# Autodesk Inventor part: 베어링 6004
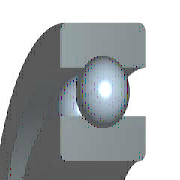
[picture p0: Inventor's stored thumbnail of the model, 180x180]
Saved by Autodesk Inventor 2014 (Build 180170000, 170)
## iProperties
IsCustomPart: 1
Created: 2012-02
Part Number: 베어링 6004
Material: 강철, 연강
Description: 깊은 그루브 볼 베어링
Document SubType Name: Modeling
Standard: KS B 2023
Designer: mduedu
Standards Organization: KS
Language: ko-KR
Size Designation: 6004 - 20 x 42 x 12
Categories: <MemberInstance><Categories><Category DisplayName="샤프트 부품" InternalName="7f7aeb1f-a693-4053-b835-cee3144e0d98" Mnemonic="SHFT"><Category DisplayName="베어링" Inter
Density: 1 g/cm^3
Appearance: Yellow
Author: mduedu
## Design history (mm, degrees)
sketch "스케치" dims "d0" = 5.72 (= -0.26 x WD + 0.26 x BD)
  geometry: L1 (3.14, 15.5)-(8.86, 15.5); L2 (6, 15.5)-(6, 12.64); L3 (6, 15.5)-(6, 18.36); L4 (3.875, 13.586)-(0, 13.586); L5 (0, 10)-(12, 10); L6 (3.875, 17.414)-(0, 17.414); L7 (0, 21)-(12, 21); L8 (12, 10)-(12, 13.586); L9 (8.125, 13.586)-(12, 13.586); L10 (8.125, 17.414)-(12, 17.414); L11 (12, 21)-(12, 17.414); L12 (-1.4, 0)-(8.4, 0) reference; L13 (0, -0.3)-(0, 5.3) reference
  constraints: 22 end point, 4 point on line, 2 collinear, 2 perpendicular, 2 symmetric about line, 1 midpoint, 1 parallel, 14 other
  dimensions: "d9" = 20 diameter of L5 L12 (= WD); "d11" = 42 diameter of L7 L12 (= BD); "d12" = 12 distance between parallel lines of L8 L13 (= KB); "d13" = 27.172 diameter of L9 L12 (= 0.326 x BD + 0.674 x WD)
revolve "본체" stored, may be unused: angle "d6" = 90 deg
revolve "볼" stored, may be unused: angle "d7" = 90 deg
pattern_circular "IDS_ARRAYBALL[SIMPL:T]" dims angle "d3" = 360 deg
body "Solid1"
fillet "모깎기1" dims "d1" = 0.6 (= KRS)
other parameters: "WD" = 20 [user parameter; used in 5 equation terms], "BD" = 42 [user parameter; used in 5 equation terms], "KB" = 12 [user parameter; used in 1 equation term], "KRS" = 0.6 [user parameter; used in 1 equation term], "d4" = 0, "d5" = 0, "d8" = 0, "d14" = 0, "d15" = 0, "BBA" = 0 [user parameter], "BC0" = 5000000 [user parameter], "BC" = 9360000 [user parameter], "BR" = 21 (= 0.5 x BD) [user parameter]
